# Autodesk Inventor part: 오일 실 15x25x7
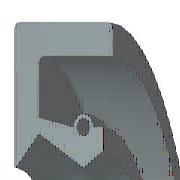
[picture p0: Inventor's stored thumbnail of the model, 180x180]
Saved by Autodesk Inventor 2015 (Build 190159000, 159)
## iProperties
Created: 2012-02
Part Number: 오일 실 15x25x7
Material: 고무
Description: 오일-실
Document SubType Name: Modeling
Standard: KS B 2804
Designer: mduedu
Standards Organization: KS
Language: ko-KR
Size Designation: D - 15 25 7
Categories: <MemberInstance><Categories><Category DisplayName="샤프트 부품" InternalName="7f7aeb1f-a693-4053-b835-cee3144e0d98" Mnemonic="SHFT"><Category DisplayName="실링" Intern
Density: 0.93 g/cm^3
Appearance: 고무 - 검은색 - 버전 1.1
IsCustomPart: 1
Author: mduedu
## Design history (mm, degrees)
revolve "본체" stored, may be unused: angle "d17" = 90 deg
revolve "스프링1" stored, may be unused: angle "d18" = 90 deg
body "Solid1"
sketch "스케치1"
  geometry: L1 (0, 12.5)-(7, 12.5); L2 (7, 10.75)-(1.75, 10.75); L3 (1.75, 9.25)-(4.9, 7.5); L4 (4.9, 7.5)-(0, 7.5); L5 (0, 0)-(9.586, 0) reference; L6 (4.9, 7.5)-(6.3, 8.375); L7 (0, 18)-(0, -3) reference; L8 (-1.941, 0)-(11.507, 0) reference; L9 (4.2, 9.6)-(1.75, 10.09); L10 (1.75, 10.09)-(1.75, 10.75); L11 (0, 12.5)-(0, 7.588); L12 (4.9, 7.5)-(0, 7.5); L13 (1.75, 9.25)-(0.152, 7.528); L14 (7, 12.5)-(7, 10.75); L15 (5.6, 9.6)-(6.3, 9.6); L16 (6.3, 9.6)-(6.3, 8.375); C1 r 0.455 at (4.9, 9.6); A1 r 0.7 centre (4.9, 9.6) between (5.6, 9.6) and (4.2, 9.6); A2 r 0.088 centre (0.088, 7.588) between (0, 7.588) and (0.152, 7.528); 1 further point
  constraints: 28 end point, 5 horizontal alignment, 5 point on line, 4 point on circle, 4 vertical alignment, 3 centre point, 3 tangent, 2 collinear, 2 horizontal, 2 perpendicular, 1 coincident, 1 parallel
  dimensions: "d0" = 25 diameter of L1 L5 (= SD2); "d1" = 1.75 distance of L1.end L2.start (= SD); "d2" = 0.91 diameter of C1 (= SPDI); "d3" = 1.4 diameter of A1 (= SPDA); "d4" = 15 diameter of L3.end L5 (= NND); "d5" = 18.5 diameter of L3.start L5 (= TKDM); "d7" = 20.18 diameter of L9.end L5 (= TKDM + 0.24 x SWDT); "d8" = 1.75 distance between parallel lines of L11 L10 (= SD); "d9" = 4.9 distance from line of L11 C1.centre (= SPDST); "d10" = 19.2 diameter of C1.centre L5 (= HLDM); "d11" = 0.0875 radius of A2 (= 0.25 x LAB); "d12" = 6.3 distance between parallel lines of L11 L16 (= SDI); "d13" = 16.75 diameter of L6.end L5 (= ABDM); "d14" = 7 distance from line of L11 L1.end (= SWDT)
fillet "모깎기1" dims "d6" = 0.3 (= RR)
other parameters: "SD2" = 25 [user parameter; used in 1 equation term], "SWDT" = 7 [user parameter; used in 2 equation terms], "RR" = 0.3 [user parameter; used in 1 equation term], "SD" = 1.75 [user parameter; used in 2 equation terms], "NND" = 15 [user parameter; used in 1 equation term], "SPDA" = 1.4 [user parameter; used in 1 equation term], "SPDI" = 0.91 [user parameter; used in 1 equation term], "TKDM" = 18.5 [user parameter; used in 2 equation terms], "HLDM" = 19.2 [user parameter; used in 1 equation term], "ABDM" = 16.75 [user parameter; used in 1 equation term], "SDI" = 6.3 [user parameter; used in 1 equation term], "SPDST" = 4.9 [user parameter; used in 1 equation term], "LAB" = 0.35 [user parameter; used in 1 equation term], "d15" = 0, "d16" = 0, "d19" = 0
